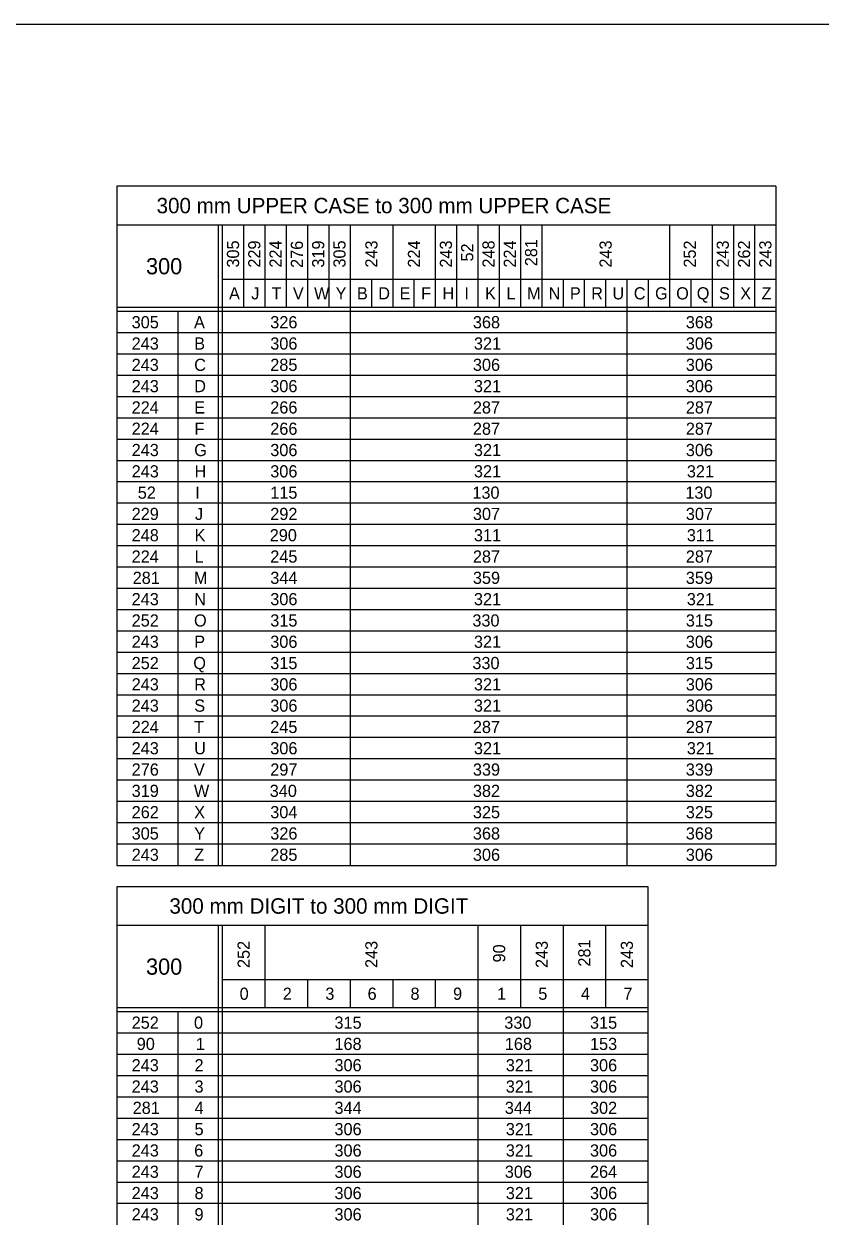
# Model space of a CAD drawing. Extents: x 637580 to 641849, y 297270 to 299646.
# Drawn here: x 637814.3 to 638010.8, y 297552.6 to 297848.6 of the extents above; entities that cross this region are included whole.
import ezdxf

# ---------------------------------------------------------------- set-up
doc = ezdxf.new("R2010")
doc.units = 0
doc.layers.add('1', color=7, linetype='Continuous')
doc.layers.add('2', color=7, linetype='Continuous')

msp = doc.modelspace()

# ---------------------------------------------------------------- linework, layer by layer
at = {"layer": '1'}
msp.add_line((637620.31, 297848.63), (638406.31, 297848.63), dxfattribs=at)
at = {"layer": '2'}
for p, q in [((637999.71, 297808.63), (637837.21, 297808.63)), ((637837.21, 297808.63), (637837.21, 297641.25)), ((637999.71, 297808.63), (637999.71, 297641.25)), ((637837.21, 297799.13), (637999.71, 297799.13)), ((637862.21, 297799.13), (637862.21, 297641.25)), ((637863.21, 297799.13), (637863.21, 297641.25)), ((637868.46, 297799.13), (637868.46, 297778.75)), ((637873.71, 297799.13), (637873.71, 297778.75)), ((637878.96, 297799.13), (637878.96, 297778.75)), ((637884.21, 297799.13), (637884.21, 297778.75)), ((637889.46, 297799.13), (637889.46, 297778.75)), ((637894.71, 297799.13), (637894.71, 297641.25)), ((637905.21, 297799.13), (637905.21, 297778.75)), ((637915.71, 297799.13), (637915.71, 297778.75)), ((637920.96, 297799.13), (637920.96, 297778.75)), ((637926.21, 297799.13), (637926.21, 297778.75)), ((637931.46, 297799.13), (637931.46, 297778.75)), ((637936.71, 297799.13), (637936.71, 297778.75)), ((637941.96, 297799.13), (637941.96, 297778.75)), ((637973.46, 297799.13), (637973.46, 297778.75)), ((637983.96, 297799.13), (637983.96, 297778.75)), ((637989.21, 297799.13), (637989.21, 297778.75)), ((637994.46, 297799.13), (637994.46, 297778.75)), ((637863.21, 297785.75), (637999.71, 297785.75)), ((637899.96, 297785.75), (637899.96, 297778.75)), ((637910.46, 297785.75), (637910.46, 297778.75)), ((637947.21, 297785.75), (637947.21, 297778.75)), ((637952.46, 297785.75), (637952.46, 297778.75)), ((637957.71, 297785.75), (637957.71, 297778.75)), ((637957.71, 297785.75), (637957.71, 297778.75)), ((637962.96, 297785.75), (637962.96, 297641.25)), ((637968.21, 297785.75), (637968.21, 297778.75)), ((637978.71, 297785.75), (637978.71, 297778.75)), ((637999.71, 297778.75), (637837.21, 297778.75)), ((637999.71, 297777.75), (637837.21, 297777.75)), ((637852.21, 297777.75), (637852.21, 297641.25)), ((637999.71, 297772.5), (637837.21, 297772.5)), ((637999.71, 297767.25), (637837.21, 297767.25)), ((637999.71, 297762), (637837.21, 297762)), ((637999.71, 297756.75), (637837.21, 297756.75)), ((637999.71, 297751.5), (637837.21, 297751.5)), ((637999.71, 297746.25), (637837.21, 297746.25)), ((637999.71, 297741), (637837.21, 297741)), ((637999.71, 297735.75), (637837.21, 297735.75)), ((637999.71, 297730.5), (637837.21, 297730.5)), ((637999.71, 297725.25), (637837.21, 297725.25)), ((637999.71, 297720), (637837.21, 297720)), ((637999.71, 297714.75), (637837.21, 297714.75)), ((637999.71, 297709.5), (637837.21, 297709.5)), ((637999.71, 297704.25), (637837.21, 297704.25)), ((637999.71, 297699), (637837.21, 297699)), ((637999.71, 297693.75), (637837.21, 297693.75)), ((637999.71, 297688.5), (637837.21, 297688.5)), ((637999.71, 297683.25), (637837.21, 297683.25)), ((637999.71, 297678), (637837.21, 297678)), ((637999.71, 297672.75), (637837.21, 297672.75)), ((637999.71, 297667.5), (637837.21, 297667.5)), ((637999.71, 297662.25), (637837.21, 297662.25)), ((637999.71, 297657), (637837.21, 297657)), ((637999.71, 297651.75), (637837.21, 297651.75)), ((637999.71, 297646.5), (637837.21, 297646.5)), ((637837.21, 297641.25), (637837.21, 297641.25)), ((637837.21, 297641.25), (637999.71, 297641.25)), ((637968.21, 297636), (637837.21, 297636)), ((637837.21, 297636), (637837.21, 297552.63)), ((637968.21, 297552.63), (637968.21, 297636)), ((637837.21, 297626.5), (637968.21, 297626.5)), ((637862.21, 297626.5), (637862.21, 297552.63)), ((637863.21, 297626.5), (637863.21, 297552.63)), ((637873.71, 297626.5), (637873.71, 297606.13)), ((637926.21, 297626.5), (637926.21, 297552.63)), ((637936.71, 297626.5), (637936.71, 297606.13)), ((637947.21, 297626.5), (637947.21, 297552.63)), ((637957.71, 297626.5), (637957.71, 297606.13)), ((637863.21, 297613.13), (637968.21, 297613.13)), ((637884.21, 297613.13), (637884.21, 297606.13)), ((637894.71, 297613.13), (637894.71, 297606.13)), ((637905.21, 297613.13), (637905.21, 297606.13)), ((637915.71, 297613.13), (637915.71, 297606.13)), ((637968.21, 297606.13), (637837.21, 297606.13)), ((637968.21, 297605.13), (637837.21, 297605.13)), ((637852.21, 297605.13), (637852.21, 297552.63)), ((637968.21, 297599.88), (637837.21, 297599.88)), ((637968.21, 297594.63), (637837.21, 297594.63)), ((637968.21, 297589.38), (637837.21, 297589.38)), ((637968.21, 297584.13), (637837.21, 297584.13)), ((637968.21, 297578.88), (637837.21, 297578.88)), ((637968.21, 297573.63), (637837.21, 297573.63)), ((637968.21, 297568.38), (637837.21, 297568.38)), ((637968.21, 297563.13), (637837.21, 297563.13)), ((637968.21, 297557.88), (637837.21, 297557.88))]:
    msp.add_line(p, q, dxfattribs=at)

# ---------------------------------------------------------------- texts
for s, height, p in [('300 mm UPPER CASE to 300 mm UPPER CASE', 3.8, (637847, 297801.98)), ('300', 4, (637844.4, 297786.94)), ('A', 3, (637864.86, 297780.75)), ('J', 3, (637870.34, 297780.75)), ('T', 3, (637875.34, 297780.75)), ('V', 3, (637880.61, 297780.75)), ('W', 3, (637885.83, 297780.75)), ('Y', 3, (637891.14, 297780.75)), ('B', 3, (637896.4, 297780.75)), ('D', 3, (637901.65, 297780.75)), ('E', 3, (637906.92, 297780.75)), ('F', 3, (637912.22, 297780.75)), ('H', 3, (637917.49, 297780.75)), ('I', 3, (637922.9, 297780.75)), ('K', 3, (637927.99, 297780.75)), ('L', 3, (637933.24, 297780.75)), ('M', 3, (637938.33, 297780.75)), ('N', 3, (637943.65, 297780.75)), ('P', 3, (637948.9, 297780.75)), ('R', 3, (637954.15, 297780.75)), ('U', 3, (637959.39, 297780.75)), ('C', 3, (637964.65, 297780.75)), ('G', 3, (637969.9, 297780.75)), ('O', 3, (637975.11, 297780.75)), ('Q', 3, (637980.18, 297780.75)), ('S', 3, (637985.67, 297780.75)), ('X', 3, (637990.89, 297780.75)), ('Z', 3, (637996.15, 297780.75)), ('305', 3, (637840.86, 297773.63)), ('A', 3, (637856.23, 297773.63)), ('326', 3, (637875.03, 297773.63)), ('368', 3, (637924.99, 297773.63)), ('368', 3, (637977.49, 297773.63)), ('243', 3, (637840.86, 297768.38)), ('B', 3, (637856.28, 297768.38)), ('306', 3, (637875.03, 297768.38)), ('321', 3, (637925.24, 297768.38)), ('306', 3, (637977.49, 297768.38)), ('243', 3, (637840.86, 297763.13)), ('C', 3, (637856.28, 297763.13)), ('285', 3, (637875.03, 297763.13)), ('306', 3, (637924.99, 297763.13)), ('306', 3, (637977.49, 297763.13)), ('243', 3, (637840.86, 297757.88)), ('D', 3, (637856.28, 297757.88)), ('306', 3, (637875.03, 297757.88)), ('321', 3, (637925.24, 297757.88)), ('306', 3, (637977.49, 297757.88)), ('224', 3, (637840.86, 297752.63)), ('E', 3, (637856.29, 297752.63)), ('266', 3, (637875.03, 297752.63)), ('287', 3, (637924.99, 297752.63)), ('287', 3, (637977.49, 297752.63)), ('224', 3, (637840.86, 297747.38)), ('F', 3, (637856.35, 297747.38)), ('266', 3, (637875.03, 297747.38)), ('287', 3, (637924.99, 297747.38)), ('287', 3, (637977.49, 297747.38)), ('243', 3, (637840.86, 297742.13)), ('G', 3, (637856.28, 297742.13)), ('306', 3, (637875.03, 297742.13)), ('321', 3, (637925.24, 297742.13)), ('306', 3, (637977.49, 297742.13)), ('243', 3, (637840.86, 297736.88)), ('H', 3, (637856.36, 297736.88)), ('306', 3, (637875.03, 297736.88)), ('321', 3, (637925.24, 297736.88)), ('321', 3, (637977.74, 297736.88)), ('52', 3, (637842.36, 297731.63)), ('I', 3, (637856.53, 297731.63)), ('115', 3, (637875.03, 297731.63)), ('130', 3, (637924.86, 297731.63)), ('130', 3, (637977.36, 297731.63)), ('229', 3, (637840.86, 297726.38)), ('J', 3, (637856.47, 297726.38)), ('292', 3, (637875.03, 297726.38)), ('307', 3, (637924.99, 297726.38)), ('307', 3, (637977.49, 297726.38)), ('248', 3, (637840.86, 297721.13)), ('K', 3, (637856.36, 297721.13)), ('290', 3, (637874.9, 297721.13)), ('311', 3, (637925.24, 297721.13)), ('311', 3, (637977.74, 297721.13)), ('224', 3, (637840.86, 297715.88)), ('L', 3, (637856.36, 297715.88)), ('245', 3, (637875.03, 297715.88)), ('287', 3, (637924.99, 297715.88)), ('287', 3, (637977.49, 297715.88)), ('281', 3, (637841.11, 297710.63)), ('M', 3, (637856.21, 297710.63)), ('344', 3, (637875.03, 297710.63)), ('359', 3, (637924.99, 297710.63)), ('359', 3, (637977.49, 297710.63)), ('243', 3, (637840.86, 297705.38)), ('N', 3, (637856.28, 297705.38)), ('306', 3, (637875.03, 297705.38)), ('321', 3, (637925.24, 297705.38)), ('321', 3, (637977.74, 297705.38)), ('252', 3, (637840.86, 297700.13)), ('O', 3, (637856.23, 297700.13)), ('315', 3, (637875.03, 297700.13)), ('330', 3, (637924.86, 297700.13)), ('315', 3, (637977.49, 297700.13)), ('243', 3, (637840.86, 297694.88)), ('P', 3, (637856.28, 297694.88)), ('306', 3, (637875.03, 297694.88)), ('321', 3, (637925.24, 297694.88)), ('306', 3, (637977.49, 297694.88)), ('252', 3, (637840.86, 297689.63)), ('Q', 3, (637856.05, 297689.63)), ('315', 3, (637875.03, 297689.63)), ('330', 3, (637924.86, 297689.63)), ('315', 3, (637977.49, 297689.63)), ('243', 3, (637840.86, 297684.38)), ('R', 3, (637856.28, 297684.38)), ('306', 3, (637875.03, 297684.38)), ('321', 3, (637925.24, 297684.38)), ('306', 3, (637977.49, 297684.38)), ('243', 3, (637840.86, 297679.13)), ('S', 3, (637856.29, 297679.13)), ('306', 3, (637875.03, 297679.13)), ('321', 3, (637925.24, 297679.13)), ('306', 3, (637977.49, 297679.13)), ('224', 3, (637840.86, 297673.88)), ('T', 3, (637856.22, 297673.88)), ('245', 3, (637875.03, 297673.88)), ('287', 3, (637924.99, 297673.88)), ('287', 3, (637977.49, 297673.88)), ('243', 3, (637840.86, 297668.63)), ('U', 3, (637856.27, 297668.63)), ('306', 3, (637875.03, 297668.63)), ('321', 3, (637925.24, 297668.63)), ('321', 3, (637977.74, 297668.63)), ('276', 3, (637840.86, 297663.38)), ('V', 3, (637856.23, 297663.38)), ('297', 3, (637875.03, 297663.38)), ('339', 3, (637924.99, 297663.38)), ('339', 3, (637977.49, 297663.38)), ('319', 3, (637840.86, 297658.13)), ('W', 3, (637856.21, 297658.13)), ('340', 3, (637874.9, 297658.13)), ('382', 3, (637924.99, 297658.13)), ('382', 3, (637977.49, 297658.13)), ('262', 3, (637840.86, 297652.88)), ('X', 3, (637856.27, 297652.88)), ('304', 3, (637875.03, 297652.88)), ('325', 3, (637924.99, 297652.88)), ('325', 3, (637977.49, 297652.88)), ('305', 3, (637840.86, 297647.63)), ('Y', 3, (637856.27, 297647.63)), ('326', 3, (637875.03, 297647.63)), ('368', 3, (637924.99, 297647.63)), ('368', 3, (637977.49, 297647.63)), ('243', 3, (637840.86, 297642.38)), ('Z', 3, (637856.28, 297642.38)), ('285', 3, (637875.03, 297642.38)), ('306', 3, (637924.99, 297642.38)), ('306', 3, (637977.49, 297642.38)), ('300 mm DIGIT to 300 mm DIGIT', 3.8, (637850.16, 297629.35)), ('300', 4, (637844.4, 297614.31)), ('0', 3, (637867.48, 297608.13)), ('2', 3, (637878.11, 297608.13)), ('3', 3, (637888.61, 297608.13)), ('6', 3, (637899.03, 297608.13)), ('8', 3, (637909.61, 297608.13)), ('9', 3, (637920.1, 297608.13)), ('1', 3, (637930.95, 297608.13)), ('5', 3, (637941.11, 297608.13)), ('4', 3, (637951.61, 297608.13)), ('7', 3, (637962.11, 297608.13)), ('252', 3, (637840.86, 297601)), ('0', 3, (637856.23, 297601)), ('315', 3, (637890.86, 297601)), ('330', 3, (637932.73, 297601)), ('315', 3, (637953.86, 297601)), ('90', 3, (637842.11, 297595.75)), ('1', 3, (637856.7, 297595.75)), ('168', 3, (637890.86, 297595.75)), ('168', 3, (637932.86, 297595.75)), ('153', 3, (637953.86, 297595.75)), ('243', 3, (637840.86, 297590.5)), ('2', 3, (637856.36, 297590.5)), ('306', 3, (637890.86, 297590.5)), ('321', 3, (637933.11, 297590.5)), ('306', 3, (637953.86, 297590.5)), ('243', 3, (637840.86, 297585.25)), ('3', 3, (637856.36, 297585.25)), ('306', 3, (637890.86, 297585.25)), ('321', 3, (637933.11, 297585.25)), ('306', 3, (637953.86, 297585.25)), ('281', 3, (637841.11, 297580)), ('4', 3, (637856.36, 297580)), ('344', 3, (637890.86, 297580)), ('344', 3, (637932.86, 297580)), ('302', 3, (637953.86, 297580)), ('243', 3, (637840.86, 297574.75)), ('5', 3, (637856.36, 297574.75)), ('306', 3, (637890.86, 297574.75)), ('321', 3, (637933.11, 297574.75)), ('306', 3, (637953.86, 297574.75)), ('243', 3, (637840.86, 297569.5)), ('6', 3, (637856.28, 297569.5)), ('306', 3, (637890.86, 297569.5)), ('321', 3, (637933.11, 297569.5)), ('306', 3, (637953.86, 297569.5)), ('243', 3, (637840.86, 297564.25)), ('7', 3, (637856.36, 297564.25)), ('306', 3, (637890.86, 297564.25)), ('306', 3, (637932.86, 297564.25)), ('264', 3, (637953.86, 297564.25)), ('243', 3, (637840.86, 297559)), ('8', 3, (637856.36, 297559)), ('306', 3, (637890.86, 297559)), ('321', 3, (637933.11, 297559)), ('306', 3, (637953.86, 297559)), ('243', 3, (637840.86, 297553.75)), ('9', 3, (637856.35, 297553.75)), ('306', 3, (637890.86, 297553.75)), ('321', 3, (637933.11, 297553.75)), ('306', 3, (637953.86, 297553.75))]:
    msp.add_text(s, height=height, dxfattribs=at).set_placement(p)
for s, p in [('305', (637867.34, 297788.59)), ('229', (637872.59, 297788.58)), ('224', (637877.84, 297788.59)), ('276', (637883.09, 297788.51)), ('319', (637888.34, 297788.58)), ('305', (637893.59, 297788.59)), ('243', (637901.46, 297788.59)), ('224', (637911.96, 297788.59)), ('243', (637919.84, 297788.59)), ('52', (637925.09, 297790.09)), ('248', (637930.34, 297788.59)), ('224', (637935.59, 297788.59)), ('281', (637940.84, 297788.93)), ('243', (637959.21, 297788.59)), ('252', (637979.96, 297788.59)), ('243', (637988.09, 297788.59)), ('262', (637993.34, 297788.59)), ('243', (637998.59, 297788.59)), ('252', (637869.96, 297615.96)), ('243', (637901.46, 297615.96)), ('243', (637943.46, 297615.96)), ('281', (637953.96, 297616.31)), ('243', (637964.46, 297615.96)), ('90', (637932.96, 297617.33))]:
    msp.add_text(s, height=3, rotation=90, dxfattribs=at).set_placement(p)

doc.saveas('drawing.dxf')
